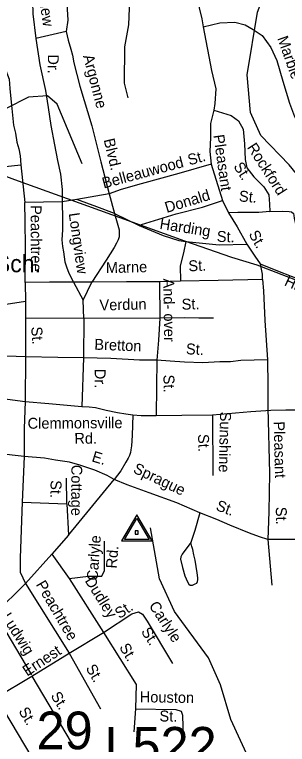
# Model space of a CAD drawing. Extents: x 1553981 to 1780076, y 812965 to 996873.
# Drawn here: x 1634606 to 1634903, y 846530 to 847325 of the extents above; entities that cross this region are included whole.
import ezdxf

# ---------------------------------------------------------------- set-up
doc = ezdxf.new("R2010")
doc.units = 0
for name, color, linetype in [('Exist Cultural Educational Facility High Label', 7, 'Continuous'), ('Exist Cultural Hospital CELL', 7, 'Continuous'), ('Exist Hydrographic Creek Single Shore', 7, 'Continuous'), ('Exist Road Non-System Type 51 Label', 7, 'Continuous'), ('Exist Road Primary Interstate Structure Cantilever Sign Number Label', 7, 'Continuous'), ('Exist Road Secondary Structure Standard Bridge Number Label', 7, 'Continuous'), ('Exist Road Secondary Type 51 Attributed', 7, 'Continuous'), ('Exist Utilities Electrical Transmission Line', 7, 'Continuous'), ('Map Preparation Border County Name Lower Right Label', 7, 'Continuous')]:
    doc.layers.add(name, color=color, linetype=linetype)

msp = doc.modelspace()

# ---------------------------------------------------------------- linework, layer by layer
at = {"layer": 'Exist Cultural Hospital CELL'}
for points in [[(1634755.69, 846751.76), (1634738.94, 846780.02), (1634722.26, 846751.76)], [(1634752.45, 846753.28), (1634725.51, 846753.28), (1634738.94, 846776.05)], [(1634740.48, 846759.1), (1634740.48, 846762.63), (1634737.45, 846762.63), (1634737.45, 846759.1)]]:
    msp.add_lwpolyline(points, close=True, dxfattribs=at)
at = {"layer": 'Exist Hydrographic Creek Single Shore'}
for points in [[(1634729.48, 847233.98), (1634725.6, 847250.07), (1634725.98, 847289.45), (1634730.48, 847313.57), (1634731.98, 847349.65), (1634730.11, 847367.74), (1634722.98, 847385.52), (1634708.6, 847406.34), (1634676.6, 847427.5), (1634658.22, 847453.73), (1634650.1, 847476.88), (1634649.6, 847519.55), (1634640.6, 847550.1), (1634642.84, 847565.65), (1634655.72, 847598.62), (1634659.1, 847617.43), (1634658.72, 847669.55), (1634666.61, 847720.68)], [(1634969.24, 847065.81), (1634945.86, 847110.59), (1634904.73, 847161.08), (1634873.85, 847192.9), (1634862.72, 847218.14), (1634858.98, 847258.84), (1634870.23, 847327.14), (1634889.6, 847377.22), (1634919.6, 847444.32), (1634923.98, 847460.23), (1634924.36, 847495.5), (1634912.98, 847581.09)], [(1634679.73, 847161.96), (1634652.35, 847226.94), (1634641.97, 847236.17), (1634621.1, 847234.55), (1634597.11, 847222.31), (1634584.6, 847223.39), (1634546.19, 847224.85), (1634537.97, 847256.34), (1634528.98, 847279.5), (1634523.09, 847317.78), (1634492.35, 847359.85)], [(1635251.23, 845900.49), (1635241.98, 845905.61), (1635222.36, 845924.47), (1635148.73, 846037.17), (1635133.36, 846064.15), (1635107.11, 846126.24), (1635100.35, 846173.96), (1635092.23, 846190.95), (1635059.23, 846226.51), (1635014.48, 846310.71), (1634938.4, 846360.17), (1634946.3, 846370.23), (1634946.3, 846412.62), (1634889.57, 846459.33), (1634877.36, 846479.45), (1634841.23, 846557.55), (1634830.22, 846595.11), (1634817.1, 846624.51), (1634780.1, 846674.92), (1634763.85, 846710.53), (1634754.1, 846766.12)]]:
    msp.add_lwpolyline(points, dxfattribs=at)
at = {"layer": 'Exist Road Secondary Type 51 Attributed'}
msp.add_lwpolyline([(1634368.51, 846931.04), (1634414.99, 846925.49), (1634455.57, 846921.12), (1634474.57, 846918.93), (1634533.83, 846913), (1634573.45, 846909.26), (1634617.65, 846903.64), (1634643.26, 846901.3), (1634679.38, 846898.21), (1634687.3, 846897.82), (1634694.06, 846896.85), (1634705.65, 846893.95), (1634718.21, 846891.63), (1634727.29, 846890.09), (1634734.63, 846888.93), (1634743.9, 846888.15), (1634749.12, 846888.15), (1634760.13, 846888.35), (1634788.06, 846888.58), (1634821.48, 846888.97), (1634862.93, 846892.53), (1634884.89, 846894.06), (1634901.24, 846894.57), (1634922.44, 846894.57)], dxfattribs=at)
at = {"layer": 'Exist Utilities Electrical Transmission Line'}
msp.add_lwpolyline([(1633983.25, 847336.25), (1634034.74, 847318.32), (1634094.15, 847296.33), (1634151.37, 847277.58), (1634234.44, 847248.26), (1634301.59, 847223.9), (1634366.5, 847200.82), (1634427.91, 847178.51), (1634440.84, 847173.85), (1634492.23, 847168.2), (1634535.17, 847163.88), (1634565.08, 847160.24), (1634605.87, 847144.98), (1634663.3, 847124.23), (1634790.89, 847078.34), (1634842.13, 847060.69), (1634869.75, 847052.33), (1634976.64, 847010.96)], dxfattribs=at)
at = {"layer": 'Map Preparation Border County Name Lower Right Label'}
for p, q in [((1634662.4, 847306.11), (1634629.36, 847298.47)), ((1634708.88, 847129.51), (1634673.87, 847123.46)), ((1634708.88, 847129.51), (1634714.92, 847108.17)), ((1634657.96, 847120.91), (1634617.22, 847119.96)), ((1634673.87, 847123.46), (1634657.96, 847120.91)), ((1634832.42, 847122.32), (1634838.83, 847108.69)), ((1634617.54, 847033.02), (1634617.86, 847012.32)), ((1634690.27, 847033.39), (1634670.37, 847033.34)), ((1634670.37, 847033.34), (1634680.87, 847013.69)), ((1634680.87, 847013.69), (1634690.27, 847033.39)), ((1634763.72, 847033.83), (1634764.09, 846994.29)), ((1634681.53, 846993.7), (1634680.87, 847013.69)), ((1634617.86, 847012.32), (1634577.19, 847006.01)), ((1634617.86, 847012.32), (1634617.96, 846952.02)), ((1634681.53, 846993.7), (1634617.89, 846994)), ((1634681.53, 846993.7), (1634681.23, 846951.12)), ((1634764.09, 846994.29), (1634681.53, 846993.7)), ((1634617.96, 846952.02), (1634576.57, 846953.58)), ((1634617.96, 846952.02), (1634617.65, 846903.64)), ((1634681.23, 846951.12), (1634679.38, 846898.21)), ((1634821.48, 846888.97), (1634821.83, 846822.94)), ((1634616.71, 846843.71), (1634565.84, 846849.13)), ((1634881.51, 846753.43), (1634885.88, 846703.66))]:
    msp.add_line(p, q, dxfattribs=at)
for points in [[(1634587.74, 847564.48), (1634604.68, 847550.62), (1634616.22, 847537.14), (1634622.76, 847512.87), (1634627, 847450.87), (1634628.92, 847431.23), (1634637, 847417.36), (1634651.59, 847400.2), (1634658.52, 847389.03), (1634660.83, 847372.09), (1634663.91, 847318.55), (1634662.4, 847306.11)], [(1634801.59, 847354.74), (1634809.66, 847319.9), (1634811.2, 847311.04)], [(1634625.28, 847351.83), (1634625.89, 847325.43), (1634629.36, 847298.47)], [(1634588.46, 847329.91), (1634591.65, 847311.86), (1634590.49, 847293.08), (1634592.8, 847280.84), (1634595.49, 847266.59), (1634600.11, 847254.27), (1634600.88, 847244.25), (1634602.03, 847232.7), (1634602.99, 847222.2), (1634603.9, 847215.18), (1634604.96, 847204.21), (1634607.09, 847195.41), (1634608.58, 847185.71), (1634610.68, 847178.59), (1634612.05, 847170.8), (1634612.83, 847160.86)], [(1634811.2, 847311.04), (1634829.45, 847315.41), (1634845.62, 847316.18), (1634856.78, 847313.48), (1634865.63, 847308.48), (1634875.25, 847301.93), (1634884.87, 847288.83), (1634891.41, 847274.58), (1634897.96, 847252.25), (1634905.27, 847227.98), (1634910.66, 847213.73), (1634926.82, 847186), (1634936.44, 847169.83), (1634947.6, 847160.58), (1634964.15, 847150.57), (1634973.38, 847142.61), (1634977.62, 847131.05), (1634979.04, 847117.67)], [(1634811.2, 847311.04), (1634820.44, 847263.67), (1634825.06, 847243.64), (1634824.01, 847227.74), (1634822.81, 847220.52)], [(1634662.4, 847306.11), (1634664.32, 847296.87), (1634667.37, 847287.02), (1634669.26, 847280.26), (1634670.45, 847272.04), (1634677.04, 847246.69), (1634690.11, 847203.66), (1634700.11, 847164.13), (1634708.88, 847129.51)], [(1634629.36, 847298.47), (1634633.59, 847269.97), (1634639.75, 847241.85), (1634642.77, 847223.31), (1634645.52, 847203.99), (1634649.69, 847182.69), (1634652.78, 847165.67), (1634656.24, 847151.04), (1634657.96, 847134.29), (1634657.96, 847120.91)], [(1634822.81, 847220.52), (1634819.2, 847206.09), (1634819.2, 847190.86), (1634818.4, 847175.63), (1634820, 847161.6)], [(1634822.81, 847220.52), (1634841.59, 847214.6), (1634849.67, 847208.83), (1634854.68, 847199.97), (1634856.22, 847183.79), (1634856.99, 847166.85), (1634858.91, 847157.6), (1634866.22, 847147.98), (1634877.38, 847137.19), (1634882.77, 847128.33), (1634883.54, 847118.32), (1634883.69, 847110.25)], [(1634415.4, 847157.39), (1634482.75, 847155.47), (1634537.78, 847155.47), (1634592.43, 847158.93), (1634612.83, 847160.86)], [(1634612.83, 847160.86), (1634617.22, 847119.96)], [(1634820, 847161.6), (1634784.95, 847151.53), (1634743.8, 847140.43), (1634721.96, 847134.05), (1634708.88, 847129.51)], [(1634820, 847161.6), (1634832.42, 847122.32)], [(1634617.54, 847033.02), (1634617.86, 847071.87), (1634617.54, 847099.26), (1634617.22, 847119.96)], [(1634657.96, 847120.91), (1634658.28, 847102.12), (1634658.28, 847090.34), (1634657.64, 847079.51), (1634658.28, 847072.19), (1634659.23, 847066.46), (1634659.87, 847061.04), (1634660.82, 847055.63), (1634662.41, 847049.9), (1634664.96, 847043.21), (1634670.37, 847033.34)], [(1634714.92, 847108.17), (1634695.67, 847115.47), (1634673.87, 847123.46)], [(1634744.08, 847096.18), (1634781.75, 847107.57), (1634810.35, 847115.12), (1634832.42, 847122.32)], [(1634883.69, 847110.25), (1634871.79, 847109.2), (1634862.8, 847109.2), (1634849.05, 847109.2), (1634838.83, 847108.69)], [(1634838.83, 847108.69), (1634848.04, 847093.46), (1634858.87, 847074.56)], [(1634883.69, 847110.25), (1634897.96, 847110.52), (1634904.84, 847110.25), (1634907.48, 847109.99), (1634909.59, 847108.14), (1634909.86, 847106.02), (1634910.39, 847102.85), (1634911.18, 847098.35), (1634912.24, 847094.65), (1634913.56, 847091.21), (1634918.58, 847083.8), (1634924.14, 847075.6), (1634928.37, 847069.51), (1634933.39, 847062.37), (1634935.5, 847057.08), (1634936.3, 847055.49), (1634936.83, 847052.32), (1634936.56, 847047.29), (1634935.77, 847043.33), (1634934.71, 847039.89), (1634934.18, 847036.71), (1634932.07, 847030.63)], [(1634714.92, 847108.17), (1634719.7, 847090.34), (1634720.01, 847086.52), (1634719.7, 847082.7), (1634718.74, 847079.51), (1634717.15, 847075.69), (1634714.6, 847071.23), (1634705.69, 847057.22), (1634690.27, 847033.39)], [(1634714.92, 847108.17), (1634741.59, 847094.88)], [(1634741.59, 847094.88), (1634767.84, 847084.02), (1634784.65, 847078.77), (1634792.35, 847077.72)], [(1634792.35, 847077.72), (1634789.9, 847065.45), (1634786.05, 847051.09), (1634786.75, 847034.27)], [(1634792.35, 847077.72), (1634828.76, 847073.86), (1634858.87, 847074.56)], [(1634858.87, 847074.56), (1634867.48, 847061.62), (1634873.3, 847053.35)], [(1634873.3, 847053.35), (1634892.15, 847045.71), (1634906.82, 847039.82), (1634923.34, 847033.54), (1634932.07, 847030.63)], [(1634873.3, 847053.35), (1634874.5, 847047.5), (1634875.39, 847041.92), (1634875.39, 847036.33)], [(1634670.37, 847033.34), (1634643.95, 847033.34), (1634617.54, 847033.02)], [(1634763.72, 847033.83), (1634728.02, 847033.83), (1634690.27, 847033.39)], [(1634786.75, 847034.27), (1634763.72, 847033.83)], [(1634875.68, 847036.33), (1634827.55, 847035.16), (1634786.75, 847034.27)], [(1634875.68, 847036.33), (1634876.85, 847023.98), (1634878.32, 846991.65), (1634881.11, 846948.74)], [(1634764.09, 846994.29), (1634762.54, 846970.36), (1634760.93, 846948.32)], [(1634822.56, 846994.29), (1634814.33, 846994.29), (1634806.69, 846994.29), (1634791.41, 846994.59), (1634764.09, 846994.29)], [(1634681.23, 846951.12), (1634653.29, 846951.39), (1634617.96, 846952.02)], [(1634760.93, 846948.32), (1634742.11, 846948.32), (1634710.87, 846950.32), (1634681.23, 846951.12)], [(1634760.93, 846948.32), (1634760.52, 846919.47), (1634760.13, 846888.35)], [(1634881.11, 846948.74), (1634852.12, 846947.95), (1634840.87, 846946.81), (1634829.47, 846946.68), (1634810.88, 846945.73), (1634790.97, 846946.31), (1634775.31, 846947.47), (1634760.93, 846948.32)], [(1634881.11, 846948.74), (1634881.41, 846920.74), (1634881.52, 846896.48)], [(1634617.65, 846903.64), (1634616.71, 846873.99), (1634616.71, 846843.71)], [(1634881.52, 846896.48), (1634883.35, 846825.45), (1634882.82, 846783.39), (1634881.51, 846753.43)], [(1634734.63, 846888.93), (1634733.86, 846866.5), (1634733.28, 846855.1), (1634732.7, 846850.85), (1634732.12, 846848.14), (1634730.96, 846844.66), (1634729.61, 846841.96), (1634727.29, 846837.32), (1634721.61, 846828.15), (1634714.46, 846818.68)], [(1634616.71, 846843.71), (1634614.2, 846794.12)], [(1634714.46, 846818.68), (1634706.73, 846823.13), (1634693.41, 846828.93), (1634676.99, 846834.04), (1634665.83, 846837.48), (1634650.57, 846839.65), (1634638.65, 846841.7), (1634616.71, 846843.71)], [(1634662.82, 846791.97), (1634662.41, 846819.93)], [(1634664.75, 846757.93), (1634714.46, 846818.68)], [(1634807.77, 846782.5), (1634782.46, 846793.13), (1634752.33, 846803.99), (1634728.56, 846812.88), (1634714.46, 846818.68)], [(1634614.2, 846794.12), (1634612.15, 846733.26), (1634612.15, 846717.63), (1634617.92, 846705.43)], [(1634614.2, 846794.12), (1634662.82, 846791.97)], [(1634662.82, 846791.97), (1634664.75, 846757.93)], [(1634807.77, 846782.5), (1634802.14, 846762.99), (1634797.93, 846750.07)], [(1634881.51, 846753.43), (1634872.43, 846756.33), (1634861.8, 846760.38), (1634840.36, 846768.89), (1634826.06, 846775.08), (1634807.77, 846782.5)], [(1634664.75, 846757.93), (1634646.66, 846737.37)], [(1634665.57, 846711.05), (1634686.53, 846713.52), (1634700.91, 846713.52), (1634703.79, 846719.68), (1634703.79, 846751.35)], [(1634926.86, 846752.65), (1634914.69, 846753.23), (1634903.3, 846753.43), (1634892.52, 846753.43), (1634881.51, 846753.43)], [(1634797.93, 846750.07), (1634788.24, 846737.49), (1634786.93, 846734.49), (1634786.65, 846732.02), (1634788.74, 846722.72), (1634791.37, 846713.94), (1634794.25, 846707.12), (1634795.7, 846704.62), (1634796.93, 846703.59), (1634799.69, 846703.79), (1634802.71, 846705), (1634804.21, 846705.72), (1634804.99, 846707.46), (1634805.28, 846709.45), (1634805.32, 846711.43), (1634804.89, 846717.21), (1634802.36, 846730.75), (1634801.21, 846736.77), (1634799.82, 846742.3), (1634798.86, 846745.55), (1634797.93, 846750.07)], [(1634646.66, 846737.37), (1634617.92, 846705.43)], [(1634646.66, 846737.37), (1634665.57, 846711.05)], [(1634617.92, 846705.43), (1634584.63, 846672.95)], [(1634617.92, 846705.43), (1634665.55, 846629.49)], [(1634665.57, 846711.05), (1634702.95, 846652.11)], [(1634584.63, 846672.95), (1634624.46, 846606.05)], [(1634702.95, 846652.11), (1634733.8, 846672.53), (1634740.79, 846674.59), (1634745.31, 846672.12), (1634750.24, 846664.31), (1634777.78, 846618.25)], [(1634665.55, 846629.49), (1634702.95, 846652.11)], [(1634702.95, 846652.11), (1634738.29, 846595.36), (1634737.47, 846569.04)], [(1634624.91, 846604.68), (1634665.55, 846629.49)], [(1634665.55, 846629.49), (1634699.66, 846569.04)], [(1634585.87, 846581.24), (1634624.91, 846604.68)], [(1634624.91, 846604.68), (1634667.61, 846532.44)], [(1634585.87, 846581.24), (1634632.68, 846502.83)], [(1634737.47, 846569.04), (1634735.82, 846543.95)], [(1634737.47, 846569.04), (1634781.44, 846568.22), (1634787.19, 846566.57), (1634788.84, 846562.05), (1634789.66, 846536.96)]]:
    msp.add_lwpolyline(points, dxfattribs=at)

# ---------------------------------------------------------------- texts
at = {"layer": 'Exist Cultural Educational Facility High Label'}
msp.add_text('Elem. Sch.', height=18.75, dxfattribs=at).set_placement((1634513.59, 847044.12))
at = {"layer": 'Exist Road Non-System Type 51 Label'}
for s, rotation, p in [('Longview', 278.0681, (1634627.85, 847377.43)), ('Marble', 289.54926, (1634891.66, 847298.83)), ('Dr.', 269.87603, (1634642.3, 847281.27)), ('Argonne', 284.63937, (1634680.46, 847279.44)), ('Blvd.', 283.42241, (1634702.93, 847188.34)), ('Pleasant', 278.09233, (1634822.23, 847193.25)), ('Rockford', 302.72611, (1634858.51, 847180.11)), ('St.', 15.53221, (1634796.21, 847160.36)), ('Belleauwood', 15.09085, (1634703.11, 847135.19)), ('St.', 302.72611, (1634843.73, 847159.38)), ('Donald', 16.82218, (1634771.6, 847108.65)), ('St.', 355.21196, (1634849.83, 847121.31)), ('Peachtree', 270.35585, (1634623.51, 847117.2)), ('Longview', 278.0681, (1634664.96, 847108.15)), ('Harding', 351.09468, (1634763.34, 847091.39)), ('St.', 357.91952, (1634825.9, 847077.35)), ('St.', 299.5267, (1634860.33, 847085.75)), ('Marne', 1.37596, (1634705.49, 847043.18)), ('St.', 2.28226, (1634795.38, 847045.1)), ('And- over', 270.74491, (1634767.88, 847037.25)), ('Harding', 335.32262, (1634898.69, 847030.27)), ('Verdun', 1.32, (1634698.57, 847002.51)), ('St.', 1.41926, (1634787.94, 847003.39)), ('St.', 273.84687, (1634624.17, 846984.64)), ('Bretton', 357.80908, (1634692.69, 846959.88)), ('St.', 357.40273, (1634792.32, 846954.94)), ('Dr.', 269.87603, (1634693.3, 846939.09)), ('St.', 271.30301, (1634767.98, 846932.58)), ('Clemmonsville', 0.3352, (1634620.31, 846873.83)), ('Sunshine', 268.63746, (1634829.75, 846892.52)), ('Pleasant', 271.47914, (1634887.84, 846881.75)), ('Rd.', 0.38453, (1634671.13, 846857.46)), ('St.', 271.44425, (1634805.63, 846867.98)), ('E.', 343.18945, (1634689.27, 846838.51)), ('Cottage', 269.80327, (1634667.85, 846834.62)), ('Sprague', 334.45821, (1634734.11, 846826.57)), ('St.', 269.07299, (1634645.35, 846817.95)), ('St.', 339.75427, (1634824.25, 846785.53)), ('St.', 271.54791, (1634890.14, 846788.72)), ('Carlyle', 85.67043, (1634696.36, 846708.23)), ('Rd.', 85.67043, (1634717.18, 846721.43)), ('Dudley', 301.97102, (1634682.13, 846708.39)), ('Peachtree', 300.34443, (1634628.97, 846704.44)), ('St.', 33.85996, (1634720.16, 846666.57)), ('Carlyle', 303.08932, (1634751.74, 846681.36)), ('Ludwig', 302.11398, (1634591.54, 846668.96)), ('St.', 303.08932, (1634743.18, 846653.13)), ('St.', 300.94853, (1634719.56, 846636.1)), ('Ernest', 33.47638, (1634619.74, 846603.96)), ('St.', 300.22343, (1634683.12, 846613.43)), ('St.', 301.74503, (1634644.94, 846583.34)), ('Houston', 359.07606, (1634742.14, 846576.21)), ('St.', 301.07422, (1634610.01, 846566.58)), ('St.', 359.07606, (1634763.61, 846555.34))]:
    msp.add_text(s, height=11.875, rotation=rotation, dxfattribs=at).set_placement(p)
at = {"layer": 'Exist Road Primary Interstate Structure Cantilever Sign Number Label'}
msp.add_text('L522', height=41.01, dxfattribs=at).set_placement((1634703.93, 846508.29))
at = {"layer": 'Exist Road Secondary Structure Standard Bridge Number Label'}
msp.add_text('29', height=41.01, dxfattribs=at).set_placement((1634630.04, 846525.05))

doc.saveas('drawing.dxf')
